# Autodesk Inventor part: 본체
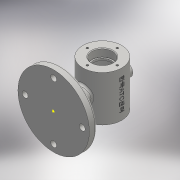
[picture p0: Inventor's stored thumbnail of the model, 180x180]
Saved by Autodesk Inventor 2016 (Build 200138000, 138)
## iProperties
Created: 2018-12
Part Number: 본체
Material: 일반
Document SubType Name: Modeling
Designer: 605-11
Density: 1 g/cm^3
Appearance: 기본값
Author: 605-11
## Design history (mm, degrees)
sketch "스케치8"
  geometry: C1 r 55 at (0, 0); 1 further point
  constraints: 1 centre point, 1 coincident
  dimensions: "d5" = 110 diameter of C1
extrude "돌출2" new body sketch "스케치8" distance "d6" = 11; taper "d7" = 0 deg
sketch "스케치9"
  geometry: L1 (55, 11)-(-55, 11) reference; L2 (-55, 11)-(0, 25.737); L3 (0, 11)-(0, 25.737); L4 (-55, 11)-(0, 11); 2 further points
  constraints: 6 end point, 1 midpoint, 1 point on line, 1 vertical
  dimensions: "d8" = 15 deg angle of L1 L2
revolve "회전1" sketch "스케치9" stored, may be unused: angle "d9" = 360 deg
sketch "스케치10"
  geometry: 1 further point
sketch "스케치12"
  geometry: C1 r 30 at (0, 75); 1 further point
  constraints: 1 centre point
  dimensions: "d13" = 60 diameter of C1; "d14" = 75 distance of point (0, 0) C1.centre
extrude "돌출4" join sketch "스케치12" stored distance "d15" = 70; taper "d16" = 0 deg
sketch "스케치11"
  geometry: C1 r 12 at (0, 0); 1 further point
  constraints: 1 centre point, 1 coincident
  dimensions: "d10" = 24 diameter of C1
extrude "돌출3" join sketch "스케치11" stored distance "d11" = 40; taper "d12" = 0 deg
sketch "스케치13"
  geometry: L1 (105, 35)-(45, 35) reference; L2 (75, 35)-(91, 35); L3 (91, 35)-(91, 23); L4 (91, 23)-(75, 23); L5 (75, 23)-(75, 35); L6 (75, 23)-(89, 23); L7 (89, 23)-(89, 20); L8 (89, 20)-(75, 20); L9 (75, 20)-(75, 23); L10 (75, 20)-(100, 20); L11 (100, 20)-(100, -20); L12 (100, -20)-(75, -20); L13 (75, -20)-(75, 20); 1 further point
  constraints: 24 end point, 6 parallel, 3 horizontal, 3 perpendicular, 1 midpoint
  dimensions: "d17" = 32 diameter of L3 L5; "d18" = 28 diameter of L7 L9; "d19" = 50 diameter of L11 L13; "d20" = 12 distance between parallel lines of L4 L1; "d21" = 3 distance between parallel lines of L8 L4; "d22" = 40 distance between parallel lines of L10 L12
revolve "회전2" sketch "스케치13" stored, may be unused: angle "d23" = 360 deg
node "작업 평면1"
sketch "스케치14"
  geometry: C1 r 10 at (0, 0); 1 further point
  constraints: 1 centre point, 1 coincident
  dimensions: "d25" = 20 diameter of C1
extrude "돌출5" join sketch "스케치14" stored distance "d26" = 70; taper "d27" = 0 deg
sketch "스케치15"
  geometry: C1 r 10 at (0, 0) reference; C2 r 5 at (0, 0)
  constraints: 1 centre point, 1 coincident
  dimensions: "d28" = 10 diameter of C2
extrude "돌출6" cut sketch "스케치15" stored distance "d29" = 0; taper "d30" = 0 deg
sketch "스케치17" dims "d31" = 46
  geometry: C1 r 30 at (0, 0) reference; 3 further points
  constraints: 1 coincident, 1 vertical alignment, 2 other
hole "구멍1" sketch "스케치17" at (0, 23) diameter "d32" = 3.242; stored, may be unused: countersink angle "d36" = 90 deg, drill point angle "d38" = 118 deg; dims "d33" = 8, "d34" = 4, "d35" = 2, "d37" = 10
sketch "스케치18" dims "d42" = 88
  geometry: C1 r 4.5 at (44, 0); 2 further points
  constraints: 1 centre point, 1 coincident, 1 horizontal alignment, 2 other
  dimensions: "d43" = 9 diameter of C1
extrude "돌출7" cut sketch "스케치18" stored distance "d44" = 70; taper "d45" = 0 deg
node "작업 평면2"
sketch "스케치19"
  geometry: C1 r 4.5 at (44, 0) reference; C2 r 7 at (44, 0); 1 further point
  constraints: 1 centre point, 1 coincident
  dimensions: "d47" = 14 diameter of C2
extrude "돌출8" cut sketch "스케치19" distance "d48" = 10; taper "d49" = 0 deg
fillet "모깎기1" dims "d53" = 3
fillet "모깎기2" dims "d54" = 0.3
chamfer "모따기1" distance "d55" = 1; stored, may be unused: second distance "d56" = 2, angle "d57" = 45 deg
sketch "스케치22"
  geometry: L1 (105, 35)-(45, 35) reference; 2 further points
  constraints: 1 other
  dimensions: "d58" = 35 distance from line of L1 point (75, 0); "d59" = 30 horizontal distance of L1.start point (75, 0)
feature "엠보싱1" sketch "스케치22" dims "d60" = 0.5, "d61" = 0
node "솔리드2"
mirror "대칭1"
pattern_circular "원형 패턴1" dims angle "d40" = 360 deg
mirror "대칭2"
pattern_circular "원형 패턴2" dims angle "d51" = 360 deg
other parameters: "d24" = 112
